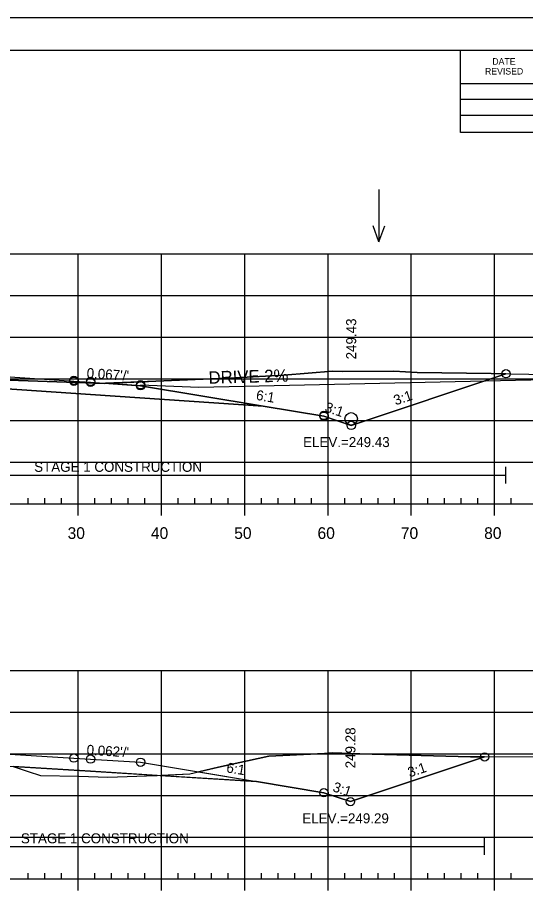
# Model space of a CAD drawing. Extents: x 1365647 to 1367999, y 387113 to 400173.
# Drawn here: x 1365916.8 to 1365977.8, y 390680.7 to 390786.1 of the extents above; entities that cross this region are included whole.
import ezdxf

# ---------------------------------------------------------------- set-up
doc = ezdxf.new("R2010")
doc.units = 0
for name, color, linetype in [('R_Alt Surface', 7, 'Continuous'), ('R_Axis', 7, 'Continuous'), ('R_Axis Annot', 7, 'Continuous'), ('R_Border', 7, 'Continuous'), ('R_Border Notes', 7, 'Continuous'), ('R_Contours', 7, 'Continuous'), ('R_Drive', 7, 'Continuous'), ('R_Exist Surface', 7, 'Continuous'), ('R_Fin Surface', 7, 'Continuous'), ('R_Fin Surface Annot', 7, 'Continuous'), ('R_Grid', 7, 'Continuous'), ('R_No Plot', 7, 'Continuous'), ('R_Proposed Const Limits', 7, 'Continuous'), ('R_Water', 7, 'Continuous'), ('R_Water Annot', 7, 'Continuous')]:
    doc.layers.add(name, color=color, linetype=linetype)

msp = doc.modelspace()

# ---------------------------------------------------------------- linework, layer by layer
at = {"layer": 'R_Alt Surface'}
for points in [[(1365843.06, 390744.76), (1365862.59, 390745.15), (1365882.51, 390743.82), (1365882.51, 390745.1), (1365894.09, 390744.33), (1365906.09, 390743.52), (1365906.09, 390742.23), (1365925.59, 390740.91), (1365946.32, 390739.52)], [(1365843.3, 390699.2), (1365862.59, 390699.59), (1365882.23, 390698.38), (1365882.23, 390699.67), (1365894.09, 390698.94), (1365905.84, 390698.22), (1365905.84, 390696.93), (1365925.59, 390695.71), (1365945.5, 390694.48)]]:
    msp.add_lwpolyline(points, dxfattribs=at)
at = {"layer": 'R_Axis'}
for p, q in [((1365918.09, 390727.79), (1365918.09, 390728.49)), ((1365920.09, 390727.79), (1365920.09, 390728.49)), ((1365922.09, 390727.79), (1365922.09, 390728.49)), ((1365926.09, 390727.79), (1365926.09, 390728.49)), ((1365928.09, 390727.79), (1365928.09, 390728.49)), ((1365930.09, 390727.79), (1365930.09, 390728.49)), ((1365932.09, 390727.79), (1365932.09, 390728.49)), ((1365936.09, 390727.79), (1365936.09, 390728.49)), ((1365938.09, 390727.79), (1365938.09, 390728.49)), ((1365940.09, 390727.79), (1365940.09, 390728.49)), ((1365942.09, 390727.79), (1365942.09, 390728.49)), ((1365946.09, 390727.79), (1365946.09, 390728.49)), ((1365948.09, 390727.79), (1365948.09, 390728.49)), ((1365950.09, 390727.79), (1365950.09, 390728.49)), ((1365952.09, 390727.79), (1365952.09, 390728.49)), ((1365956.09, 390727.79), (1365956.09, 390728.49)), ((1365958.09, 390727.79), (1365958.09, 390728.49)), ((1365960.09, 390727.79), (1365960.09, 390728.49)), ((1365962.09, 390727.79), (1365962.09, 390728.49)), ((1365966.09, 390727.79), (1365966.09, 390728.49)), ((1365968.09, 390727.79), (1365968.09, 390728.49)), ((1365970.09, 390727.79), (1365970.09, 390728.49)), ((1365972.09, 390727.79), (1365972.09, 390728.49)), ((1365976.09, 390727.79), (1365976.09, 390728.49)), ((1365749.09, 390727.79), (1366039.09, 390727.79)), ((1365924.09, 390726.39), (1365924.09, 390727.79)), ((1365934.09, 390726.39), (1365934.09, 390727.79)), ((1365944.09, 390726.39), (1365944.09, 390727.79)), ((1365954.09, 390726.39), (1365954.09, 390727.79)), ((1365964.09, 390726.39), (1365964.09, 390727.79)), ((1365974.09, 390726.39), (1365974.09, 390727.79)), ((1365749.09, 390682.79), (1366039.09, 390682.79)), ((1365918.09, 390682.79), (1365918.09, 390683.49)), ((1365920.09, 390682.79), (1365920.09, 390683.49)), ((1365922.09, 390682.79), (1365922.09, 390683.49)), ((1365924.09, 390681.39), (1365924.09, 390682.79)), ((1365926.09, 390682.79), (1365926.09, 390683.49)), ((1365928.09, 390682.79), (1365928.09, 390683.49)), ((1365930.09, 390682.79), (1365930.09, 390683.49)), ((1365932.09, 390682.79), (1365932.09, 390683.49)), ((1365934.09, 390681.39), (1365934.09, 390682.79)), ((1365936.09, 390682.79), (1365936.09, 390683.49)), ((1365938.09, 390682.79), (1365938.09, 390683.49)), ((1365940.09, 390682.79), (1365940.09, 390683.49)), ((1365942.09, 390682.79), (1365942.09, 390683.49)), ((1365944.09, 390681.39), (1365944.09, 390682.79)), ((1365946.09, 390682.79), (1365946.09, 390683.49)), ((1365948.09, 390682.79), (1365948.09, 390683.49)), ((1365950.09, 390682.79), (1365950.09, 390683.49)), ((1365952.09, 390682.79), (1365952.09, 390683.49)), ((1365954.09, 390681.39), (1365954.09, 390682.79)), ((1365956.09, 390682.79), (1365956.09, 390683.49)), ((1365958.09, 390682.79), (1365958.09, 390683.49)), ((1365960.09, 390682.79), (1365960.09, 390683.49)), ((1365962.09, 390682.79), (1365962.09, 390683.49)), ((1365964.09, 390681.39), (1365964.09, 390682.79)), ((1365966.09, 390682.79), (1365966.09, 390683.49)), ((1365968.09, 390682.79), (1365968.09, 390683.49)), ((1365970.09, 390682.79), (1365970.09, 390683.49)), ((1365972.09, 390682.79), (1365972.09, 390683.49)), ((1365974.09, 390681.39), (1365974.09, 390682.79)), ((1365976.09, 390682.79), (1365976.09, 390683.49))]:
    msp.add_line(p, q, dxfattribs=at)
at = {"layer": 'R_Border'}
for p, q in [((1365736.09, 390782.25), (1366052.27, 390782.25)), ((1365970.01, 390772.37), (1365970.01, 390782.25)), ((1365970.01, 390778.23), (1366009.17, 390778.23)), ((1365970.01, 390776.37), (1366009.17, 390776.37)), ((1365970.01, 390772.37), (1365970.01, 390774.43)), ((1365970.01, 390774.43), (1366009.17, 390774.43)), ((1366052.27, 390772.37), (1365970.01, 390772.37))]:
    msp.add_line(p, q, dxfattribs=at)
at = {"layer": 'R_Contours'}
for p, q in [((1365975.43, 390743.4), (1365973.68, 390743.43)), ((1365931.59, 390741.97), (1365927.37, 390742.26)), ((1365927.37, 390742.26), (1365931.59, 390741.97)), ((1365946.32, 390739.52), (1365931.59, 390741.97)), ((1365931.59, 390741.97), (1365946.32, 390739.52)), ((1365938.57, 390695.64), (1365945.5, 390694.48))]:
    msp.add_line(p, q, dxfattribs=at)
for points in [[(1365906.09, 390743.43), (1365911, 390742.92), (1365912.34, 390742.78), (1365912.76, 390742.71), (1365912.87, 390742.75), (1365913.13, 390742.68), (1365916.94, 390742.61), (1365927.3, 390742.25), (1365933.44, 390742.53), (1365942.92, 390742.91), (1365948.77, 390743.25), (1365954.62, 390743.7), (1365955.83, 390743.69), (1365962.01, 390743.73), (1365964.78, 390743.54), (1365973.68, 390743.43), (1365975.43, 390743.4), (1365956.87, 390737.21), (1365953.59, 390738.31), (1365946.32, 390739.52), (1365925.59, 390740.91), (1365906.09, 390742.23)], [(1365933.57, 390695.22), (1365937.52, 390695.4), (1365940.93, 390696.19), (1365947, 390697.51), (1365953.67, 390697.85), (1365954.68, 390697.91), (1365957.9, 390697.8), (1365971.19, 390697.43), (1365972.88, 390697.44), (1365956.78, 390692.07), (1365953.59, 390693.14), (1365945.5, 390694.48)], [(1365916.35, 390696.28), (1365918.09, 390695.7), (1365919.59, 390695.21), (1365924.17, 390695.11), (1365927.67, 390694.99), (1365932.3, 390695.16), (1365933.57, 390695.22), (1365925.59, 390695.71)]]:
    msp.add_lwpolyline(points, close=True, dxfattribs=at)
for points in [[(1365973.68, 390743.43), (1365964.78, 390743.54), (1365962.01, 390743.73), (1365955.83, 390743.69), (1365954.62, 390743.7), (1365948.77, 390743.25), (1365942.92, 390742.91), (1365933.44, 390742.53), (1365927.37, 390742.26)], [(1365927.37, 390742.26), (1365927.3, 390742.25), (1365916.94, 390742.61), (1365913.13, 390742.68), (1365912.87, 390742.75), (1365912.76, 390742.71), (1365912.34, 390742.78), (1365911, 390742.92), (1365906.09, 390743.43)], [(1365946.32, 390739.52), (1365953.59, 390738.31), (1365956.87, 390737.21), (1365975.43, 390743.4)], [(1365906.09, 390742.23), (1365925.59, 390740.91), (1365946.32, 390739.52)], [(1365972.88, 390697.44), (1365971.19, 390697.43), (1365957.9, 390697.8), (1365954.68, 390697.91), (1365953.67, 390697.85), (1365947, 390697.51), (1365940.93, 390696.19), (1365938.57, 390695.64)], [(1365945.5, 390694.48), (1365953.59, 390693.14), (1365956.78, 390692.07), (1365972.88, 390697.44)]]:
    msp.add_lwpolyline(points, dxfattribs=at)
at = {"layer": 'R_Drive'}
for p, q in [((1365938.59, 390741.8), (1365994.09, 390743.04)), ((1365931.59, 390742.08), (1365938.59, 390741.8))]:
    msp.add_line(p, q, dxfattribs=at)
at = {"layer": 'R_Exist Surface'}
for points in [[(1365913.13, 390742.68), (1365916.94, 390742.61), (1365927.3, 390742.25), (1365933.44, 390742.53), (1365942.92, 390742.91), (1365948.77, 390743.25), (1365954.62, 390743.7), (1365955.83, 390743.69), (1365962.01, 390743.73), (1365964.78, 390743.54), (1365973.68, 390743.43), (1365980.49, 390743.33)], [(1365916.29, 390696.3), (1365918.09, 390695.7), (1365919.59, 390695.21), (1365924.17, 390695.11), (1365927.67, 390694.99), (1365932.3, 390695.16), (1365937.52, 390695.4), (1365940.93, 390696.19), (1365947, 390697.51), (1365953.67, 390697.85), (1365954.68, 390697.91), (1365957.9, 390697.8), (1365971.19, 390697.43), (1365991.97, 390697.54)]]:
    msp.add_lwpolyline(points, dxfattribs=at)
at = {"layer": 'R_Fin Surface'}
for points in [[(1365828.73, 390745.31), (1365834.59, 390743.35), (1365843.06, 390744.76), (1365856.59, 390747.02), (1365862.59, 390746.62), (1365864.59, 390746.48), (1365894.09, 390744.5), (1365923.59, 390742.51), (1365925.59, 390742.38), (1365931.59, 390741.97), (1365946.32, 390739.52), (1365953.59, 390738.31), (1365956.87, 390737.21), (1365975.43, 390743.4)], [(1365856.59, 390747.02), (1365862.59, 390746.62), (1365864.59, 390746.48), (1365894.09, 390744.5), (1365923.59, 390742.51), (1365925.59, 390742.38), (1365931.59, 390741.97)], [(1365828.3, 390699.85), (1365834.59, 390697.75), (1365843.3, 390699.2), (1365856.59, 390701.42), (1365862.59, 390701.05), (1365864.59, 390700.93), (1365894.09, 390699.11), (1365923.59, 390697.29), (1365925.59, 390697.17), (1365931.59, 390696.8), (1365945.5, 390694.48), (1365953.59, 390693.14), (1365956.78, 390692.07), (1365972.88, 390697.44)], [(1365856.59, 390701.42), (1365862.59, 390701.05), (1365864.59, 390700.93), (1365894.09, 390699.11), (1365923.59, 390697.29), (1365925.59, 390697.17), (1365931.59, 390696.8)]]:
    msp.add_lwpolyline(points, dxfattribs=at)
at = {"layer": 'R_Grid'}
for p, q in [((1365749.09, 390757.79), (1366039.09, 390757.79)), ((1365924.09, 390727.79), (1365924.09, 390757.79)), ((1365934.09, 390727.79), (1365934.09, 390757.79)), ((1365944.09, 390727.79), (1365944.09, 390757.79)), ((1365954.09, 390727.79), (1365954.09, 390757.79)), ((1365964.09, 390727.79), (1365964.09, 390757.79)), ((1365974.09, 390727.79), (1365974.09, 390757.79)), ((1365749.09, 390752.79), (1366039.09, 390752.79)), ((1365749.09, 390747.79), (1366039.09, 390747.79)), ((1365749.09, 390742.79), (1366039.09, 390742.79)), ((1365749.09, 390737.79), (1366039.09, 390737.79)), ((1365749.09, 390732.79), (1366039.09, 390732.79)), ((1365749.09, 390727.79), (1366039.09, 390727.79)), ((1365749.09, 390707.79), (1366039.09, 390707.79)), ((1365924.09, 390682.79), (1365924.09, 390707.79)), ((1365934.09, 390682.79), (1365934.09, 390707.79)), ((1365944.09, 390682.79), (1365944.09, 390707.79)), ((1365954.09, 390682.79), (1365954.09, 390707.79)), ((1365964.09, 390682.79), (1365964.09, 390707.79)), ((1365974.09, 390682.79), (1365974.09, 390707.79)), ((1365749.09, 390702.79), (1366039.09, 390702.79)), ((1365749.09, 390697.79), (1366039.09, 390697.79)), ((1365749.09, 390692.79), (1366039.09, 390692.79)), ((1365749.09, 390687.79), (1366039.09, 390687.79)), ((1365749.09, 390682.79), (1366039.09, 390682.79))]:
    msp.add_line(p, q, dxfattribs=at)
at = {"layer": 'R_No Plot'}
msp.add_line((1365723.69, 390786.14), (1366057.03, 390786.14), dxfattribs=at)
msp.add_lwpolyline([(1365723.69, 390786.14), (1366057.03, 390786.14), (1366057.03, 390572.8), (1365723.69, 390572.8)], close=True, dxfattribs=at)
for centre in [(1365975.45, 390743.4), (1365975.45, 390743.4), (1365923.59, 390742.62), (1365923.59, 390742.62), (1365923.59, 390742.62), (1365923.59, 390742.51), (1365923.59, 390742.51), (1365925.59, 390742.49), (1365925.59, 390742.49), (1365925.59, 390742.49), (1365925.59, 390742.38), (1365925.59, 390742.38), (1365931.59, 390742.08), (1365931.59, 390742.08), (1365931.59, 390742.08), (1365931.59, 390741.97), (1365931.59, 390741.97), (1365953.59, 390738.41), (1365953.59, 390738.41), (1365953.59, 390738.41), (1365953.59, 390738.31), (1365953.59, 390738.31), (1365956.87, 390737.21), (1365956.87, 390737.21), (1365923.59, 390697.29), (1365923.59, 390697.29), (1365923.59, 390697.29), (1365923.59, 390697.29), (1365923.59, 390697.29), (1365925.59, 390697.17), (1365925.59, 390697.17), (1365925.59, 390697.17), (1365925.59, 390697.17), (1365925.59, 390697.17), (1365931.59, 390696.8), (1365931.59, 390696.8), (1365931.59, 390696.8), (1365931.59, 390696.8), (1365931.59, 390696.8), (1365972.89, 390697.44), (1365972.89, 390697.44), (1365953.59, 390693.14), (1365953.59, 390693.14), (1365953.59, 390693.14), (1365953.59, 390693.14), (1365953.59, 390693.14), (1365956.78, 390692.07), (1365956.78, 390692.07)]:
    msp.add_circle(centre, 0.5, dxfattribs=at)
at = {"layer": 'R_Proposed Const Limits'}
for points in [[(1365956.87, 390737.21), (1365975.45, 390743.4)], [(1365956.78, 390692.07), (1365972.89, 390697.44)]]:
    msp.add_lwpolyline(points, dxfattribs=at)
at = {"layer": 'R_Water'}
for p, q in [((1365975.45, 390730.25), (1365975.45, 390732.25)), ((1365882.51, 390731.25), (1365975.45, 390731.25)), ((1365882.23, 390686.68), (1365972.89, 390686.68)), ((1365972.89, 390685.68), (1365972.89, 390687.68))]:
    msp.add_line(p, q, dxfattribs=at)
msp.add_circle((1365956.87, 390738), 0.75, dxfattribs=at)
at = {"layer": 'R_Water Annot'}
for p, q in [((1365960.19, 390765.53), (1365960.19, 390759.25)), ((1365960.19, 390759.25), (1365959.49, 390761.17)), ((1365960.19, 390759.25), (1365960.89, 390761.17))]:
    msp.add_line(p, q, dxfattribs=at)

# ---------------------------------------------------------------- texts
at = {"layer": 'R_Axis Annot'}
for s, p in [('30', (1365922.83, 390723.59)), ('40', (1365932.83, 390723.59)), ('50', (1365942.83, 390723.59)), ('60', (1365952.83, 390723.59)), ('70', (1365962.83, 390723.59)), ('80', (1365972.83, 390723.59))]:
    msp.add_text(s, height=1.4, dxfattribs=at).set_placement(p)
at = {"layer": 'R_Border'}
for s, p in [('DATE', (1365973.81, 390780.49)), ('REVISED', (1365972.93, 390779.31))]:
    msp.add_text(s, height=0.782, rotation=360, dxfattribs=at).set_placement(p)
at = {"layer": 'R_Border Notes'}
for s, p in [('ELEV.=249.43', (1365951.1, 390734.61)), ('ELEV.=249.29', (1365951, 390689.47))]:
    msp.add_text(s, height=1.2, dxfattribs=at).set_placement(p)
at = {"layer": 'R_Drive'}
msp.add_text('DRIVE 2%', height=1.5, rotation=1.5543, dxfattribs=at).set_placement((1365939.77, 390742.2))
at = {"layer": 'R_Fin Surface Annot'}
for s, rotation, p in [('249.43', 90, (1365957.47, 390745.13)), ("0.067'/'", 356.1504, (1365925.09, 390742.91)), ('6:1', 350.5377, (1365945.39, 390740.29)), ('3:1', 18.4349, (1365962.2, 390739.61)), ('3:1', 341.5651, (1365953.62, 390738.9)), ('249.28', 90, (1365957.38, 390696.07)), ("0.062'/'", 356.4788, (1365925.09, 390697.7)), ('6:1', 350.5377, (1365941.83, 390695.6)), ('3:1', 18.4349, (1365963.89, 390694.97)), ('3:1', 341.5651, (1365954.56, 390693.34))]:
    msp.add_text(s, height=1.2, rotation=rotation, dxfattribs=at).set_placement(p)
at = {"layer": 'R_Water'}
for p in [(1365918.82, 390731.64), (1365917.23, 390687.07)]:
    msp.add_text('STAGE 1 CONSTRUCTION', height=1.2, dxfattribs=at).set_placement(p)

doc.saveas('drawing.dxf')
